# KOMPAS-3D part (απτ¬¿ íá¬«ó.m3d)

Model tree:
1. Эскиз:1
2. Операция выдавливания:1
     Расстояние 1 = 0.1
3. Эскиз:2
4. Операция выдавливания:2
     Расстояние 1 = 1.5
5. Эскиз:3
6. Вырезать элемент выдавливания:1
     Расстояние 1 = 7
7. Скругление:1
     Радиус = 0.5
8. Смещенная плоскость:2
     Расстояние = 0.3
9. Эскиз:4
10. Операция выдавливания:3
     Расстояние 1 = 1
11. Скругление:2
     Радиус = 0.2
12. Скругление:3
     Радиус = 0.2
13. Скругление:4
     Радиус = 0.2
14. Скругление:5
     Радиус = 0.1
15. Скругление:6
     Радиус = 0.1

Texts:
  Сплав АЛ8  ГОСТ 1583-93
